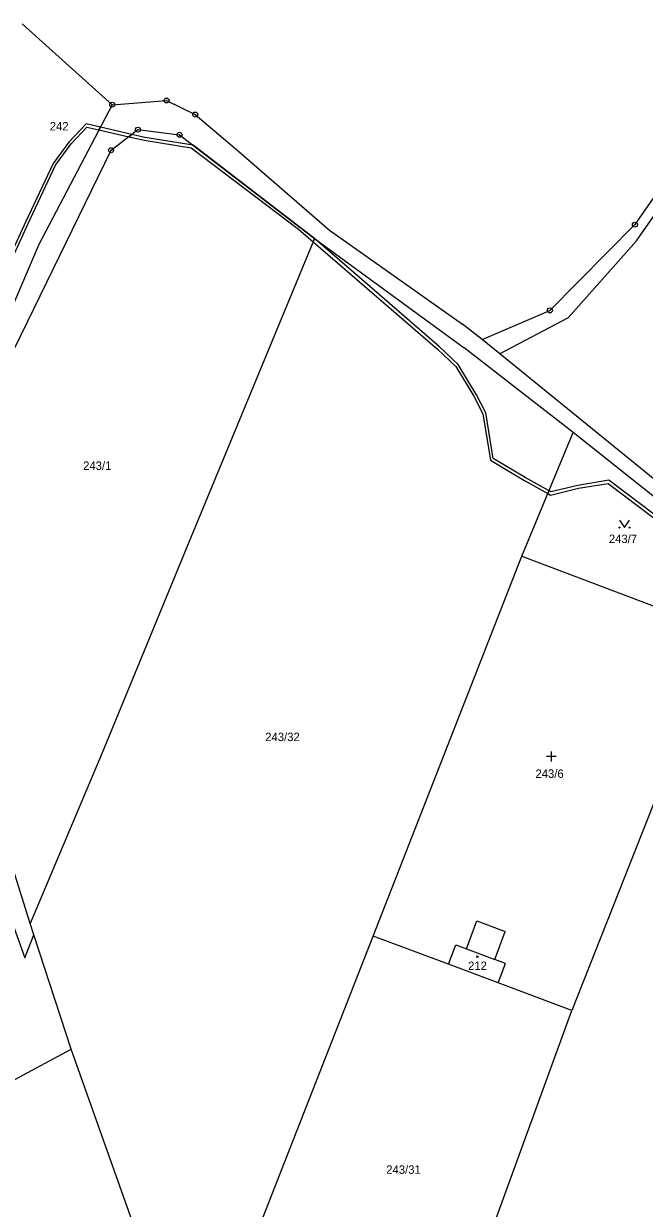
# Model space of a CAD drawing. Extents: x -701211 to -698780, y -1014269 to -1012378.
# Drawn here: x -700798.3 to -700673.2, y -1012938.3 to -1012699.5 of the extents above; entities that cross this region are included whole.
import ezdxf
from ezdxf.enums import TextEntityAlignment as Align

# ---------------------------------------------------------------- set-up
doc = ezdxf.new("R2010")
doc.units = 0
doc.header["$LTSCALE"] = 0.68
for name, color, linetype, lineweight in [('1', 7, 'Continuous', 25), ('13', 7, 'Continuous', 13), ('3', 7, 'Continuous', 25), ('4', 7, 'Continuous', 13), ('5', 7, 'Continuous', 25), ('8', 7, 'Continuous', 25)]:
    doc.layers.add(name, color=color, linetype=linetype, lineweight=lineweight)
doc.layers.add('2', color=7, linetype='Continuous')

msp = doc.modelspace()

# ---------------------------------------------------------------- linework, layer by layer
at = {"layer": '1'}
for p, q in [((-700798.64, -1012699.51), (-700780.48, -1012715.84)), ((-700647.98, -1012700.85), (-700675.08, -1012740.02)), ((-700780.48, -1012715.84), (-700769.51, -1012714.99)), ((-700769.51, -1012714.99), (-700763.73, -1012717.83)), ((-700780.48, -1012715.84), (-700795.24, -1012744.03)), ((-700763.73, -1012717.83), (-700755.39, -1012724.89)), ((-700780.71, -1012725.02), (-700775.29, -1012720.87)), ((-700775.29, -1012720.87), (-700766.9, -1012721.9)), ((-700766.9, -1012721.9), (-700739.68, -1012742.78)), ((-700800.19, -1012765.01), (-700780.71, -1012725.02)), ((-700755.39, -1012724.89), (-700736.63, -1012741.12)), ((-700674.73, -1012743.28), (-700667.91, -1012733.49)), ((-700736.63, -1012741.12), (-700709.83, -1012760.07)), ((-700675.08, -1012740.02), (-700692.23, -1012757.3)), ((-700795.24, -1012744.03), (-700803.07, -1012762.31)), ((-700739.68, -1012742.78), (-700764.98, -1012803.91)), ((-700739.68, -1012742.78), (-700709.49, -1012764.86)), ((-700674.73, -1012743.28), (-700688.51, -1012758.77)), ((-700705.91, -1012763.16), (-700692.23, -1012757.3)), ((-700705.91, -1012763.16), (-700709.83, -1012760.07)), ((-700688.51, -1012758.77), (-700702.34, -1012766.06)), ((-700702.34, -1012766.06), (-700705.91, -1012763.16)), ((-700687.54, -1012781.89), (-700709.49, -1012764.86)), ((-700622.44, -1012831.04), (-700702.34, -1012766.06)), ((-700697.86, -1012806.86), (-700687.54, -1012781.89)), ((-700652.41, -1012809.92), (-700687.54, -1012781.89)), ((-700764.98, -1012803.91), (-700782.51, -1012846.49)), ((-700727.83, -1012883.45), (-700697.86, -1012806.86)), ((-700697.86, -1012806.86), (-700657.67, -1012822.05)), ((-700657.67, -1012822.05), (-700687.77, -1012898.43)), ((-700782.51, -1012846.49), (-700797, -1012880.92)), ((-700797, -1012880.92), (-700807.25, -1012848.34)), ((-700800.3, -1012881.65), (-700798.09, -1012887.81)), ((-700796.29, -1012883.18), (-700797, -1012880.92)), ((-700709.03, -1012886), (-700706.93, -1012880.38)), ((-700706.93, -1012880.38), (-700701.21, -1012882.51)), ((-700703.32, -1012888.13), (-700701.21, -1012882.51)), ((-700798.09, -1012887.81), (-700796.29, -1012883.18)), ((-700788.72, -1012906.25), (-700796.29, -1012883.18)), ((-700758.04, -1012960.3), (-700727.83, -1012883.45)), ((-700712.66, -1012889.12), (-700727.83, -1012883.45)), ((-700712.66, -1012889.12), (-700711.18, -1012885.19)), ((-700711.18, -1012885.19), (-700709.03, -1012886)), ((-700702.63, -1012892.87), (-700712.66, -1012889.12)), ((-700701.16, -1012888.94), (-700703.32, -1012888.13)), ((-700702.63, -1012892.87), (-700701.16, -1012888.94)), ((-700687.77, -1012898.43), (-700702.63, -1012892.87)), ((-700720.09, -1012987.07), (-700687.77, -1012898.43)), ((-700840.69, -1012933.93), (-700788.72, -1012906.25)), ((-700776.39, -1012941.06), (-700788.72, -1012906.25))]:
    msp.add_line(p, q, dxfattribs=at)
at = {"layer": '13'}
msp.add_lwpolyline([(-700802.93, -1012751.91), (-700797.45, -1012739.79), (-700791.89, -1012728.02), (-700788.75, -1012723.75), (-700785.56, -1012720.35), (-700783.14, -1012720.91), (-700782.85, -1012720.36), (-700785.76, -1012719.69), (-700789.21, -1012723.37), (-700792.41, -1012727.72), (-700797.99, -1012739.55), (-700802.91, -1012750.41)], dxfattribs=at)
for points in [[(-700777.15, -1012722.29), (-700776.53, -1012721.82), (-700782.85, -1012720.36), (-700783.14, -1012720.91)], [(-700739.96, -1012743.46), (-700739.68, -1012742.78), (-700764.17, -1012724), (-700773.93, -1012722.42), (-700776.53, -1012721.82), (-700777.15, -1012722.29), (-700774.03, -1012723.02), (-700764.55, -1012724.54), (-700742.93, -1012740.9)], [(-700739.68, -1012742.78), (-700739.96, -1012743.46), (-700714.89, -1012765.1), (-700711.22, -1012768.62), (-700707.56, -1012774.59), (-700705.72, -1012778.15), (-700704.23, -1012787.51), (-700697.51, -1012791.52), (-700692.64, -1012794.22), (-700692.4, -1012793.66), (-700697.21, -1012791), (-700703.69, -1012787.13), (-700705.14, -1012777.97), (-700707.04, -1012774.29), (-700710.74, -1012768.24), (-700714.49, -1012764.66)], [(-700662.06, -1012806.12), (-700657.62, -1012810.26), (-700655.32, -1012809.41), (-700653.93, -1012808.71), (-700651.44, -1012807.46), (-700651.95, -1012807.04), (-700654.45, -1012808.3), (-700655.56, -1012808.85), (-700657.48, -1012809.56), (-700661.68, -1012805.66), (-700680.31, -1012791.53), (-700686.61, -1012792.57), (-700692.01, -1012793.88), (-700692.4, -1012793.66), (-700692.64, -1012794.22), (-700692.09, -1012794.52), (-700686.49, -1012793.15), (-700680.47, -1012792.17)]]:
    msp.add_lwpolyline(points, close=True, dxfattribs=at)
at = {"layer": '3'}
for p, q in [((-700691.93, -1012848.24), (-700691.93, -1012846.24)), ((-700690.929, -1012847.241), (-700692.931, -1012847.241))]:
    msp.add_line(p, q, dxfattribs=at)
msp.add_lwpolyline([(-700678.2, -1012799.579), (-700677.2, -1012801.08), (-700676.2, -1012799.579)], dxfattribs=at)
for centre in [(-700678.2, -1012801.0795), (-700676.2, -1012801.0795)]:
    msp.add_circle(centre, 0.1, dxfattribs=at)
at = {"layer": '4'}
msp.add_line((-700709.03, -1012886), (-700703.32, -1012888.13), dxfattribs=at)
at = {"layer": '5'}
msp.add_circle((-700706.8568, -1012887.5792), 0.175, dxfattribs=at)
at = {"layer": '8'}
for centre, radius in [((-700780.48, -1012715.8399), 0.5), ((-700769.51, -1012714.9899), 0.5), ((-700769.51, -1012714.9899), 0.0303), ((-700780.48, -1012715.8399), 0.0303), ((-700763.73, -1012717.8299), 0.5), ((-700763.73, -1012717.8299), 0.0303), ((-700775.29, -1012720.8699), 0.5), ((-700775.29, -1012720.8699), 0.0303), ((-700766.9, -1012721.8999), 0.5), ((-700766.9, -1012721.8999), 0.0303), ((-700780.71, -1012725.0199), 0.5), ((-700780.71, -1012725.0199), 0.0303), ((-700675.08, -1012740.0199), 0.5), ((-700675.08, -1012740.0199), 0.0303), ((-700692.23, -1012757.2999), 0.5), ((-700692.23, -1012757.2999), 0.0303)]:
    msp.add_circle(centre, radius, dxfattribs=at)

# ---------------------------------------------------------------- texts
at = {"layer": '2'}
for s, p in [('242', (-700791.169, -1012721.035)), ('243/1', (-700783.49, -1012789.445)), ('243/32', (-700746.14, -1012844.125)), ('243/31', (-700721.74, -1012931.345))]:
    msp.add_text(s, height=1.7, dxfattribs=at).set_placement(p, align=Align.CENTER)
for s, p in [('243/7', (-700680.34, -1012804.205)), ('243/6', (-700695.13, -1012851.535)), ('212', (-700708.72, -1012890.265))]:
    msp.add_text(s, height=1.7, dxfattribs=at).set_placement(p)

doc.saveas('drawing.dxf')
